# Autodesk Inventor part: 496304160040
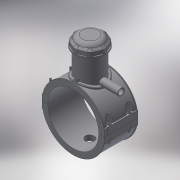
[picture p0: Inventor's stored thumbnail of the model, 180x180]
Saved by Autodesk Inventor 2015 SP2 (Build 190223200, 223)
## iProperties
Created: 2017-07
Part Number: 496304160040
Material: Generic
Description: PLASSON TAPPING SADDLE 160x40
Document SubType Name: Modeling
Designer: KIM
Mass: 1043.31 g
Surface Area: 2388.5 cm^2
Volume: 1043.31 cm^3
Density: 1 g/cm^3
Appearance: Default
Author: KIM
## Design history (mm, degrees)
derived "496304.ipt"
feature "Solid1::496304.ipt"
feature "Solid2::496304.ipt"
feature "Solid4::496304.ipt"
feature "Solid5::496304.ipt"
tag "TaggingFeature1"
body "Solid1"
body "Solid2"
other parameters: "B_" = 199, "L_" = 118, "d_t" = 6, "H_2" = 138, "H_1" = 21, "H_" = 157, "d1" = 182.4, "d148" = 2.4, "d160" = 2.4, "d169" = 3.375, "d192" = 6.3, "d2" = 199, "d4" = 118, "d5" = 0, "d6" = 0.1, "d8" = 0, "d19" = 6, "d20" = 6, "d21" = 70.8, "d23" = 0, "d24" = 35.4, "d26" = 0, "d29" = 3, "d30" = 53.33333, "d31" = 6, "d32" = 0, "d33" = 0, "d34" = 0.6, "d40" = 94.848, "d41" = 72, "d43" = 0, "d45" = 0, "d47" = 162, "d70" = 15, "d72" = 0, "d73" = 6, "d75" = 5, "d76" = 0, "d77" = 8, "d79" = 15, "d80" = 47.2, "d82" = 5 deg, "d84" = 4, "d85" = 14, "d86" = 0, "d87" = 3, "d88" = 0, "d89" = 1, "d90" = 1, "d91" = 94.4, "d92" = 0, "d93" = 0.5, "d94" = 84.21053, "d96" = 186.048, "d97" = 2.36, "d98" = 0, "d102" = 1.6, "d120" = 140 deg, "d121" = 24.228, "d122" = 20 deg, "d123" = 364.8, "d124" = 109.44, "d126" = 0, "d143" = 164.8, "d145" = 17.23077, "d149" = 2.4, "d150" = 18.95385, "d153" = 118, "d154" = 0, "d156" = 91.2, "d157" = 160 deg, "d159" = 4.48, "d161" = 2.4, "d162" = 70.8, "d163" = 0, "d167" = 16, "d168" = 88.97561, "d170" = 3.375, "d172" = 0, "d173" = 1, "d176" = 20 deg, "d177" = 11.2, "d178" = 22.4, "d180" = 0, "d183" = 8.96, "d184" = 8.96, "d185" = 38.35, "d186" = 38.35, "d187" = 91.2, "d188" = 6.72, "d189" = 11.2, "d190" = 0, "d191" = 136.8, "d193" = 6.3, "d194" = 4.13, "d195" = 90 deg, "d197" = 0, "d199" = 0, "d200" = 11.2, "d202" = 0, "d203" = 138, "d204" = 68.4, "d205" = 50.4, "d206" = 61.2, "d207" = 103.5, "d208" = 107.64, "d209" = 128.34, "d210" = 61.92, "d211" = 72, "d212" = 57.6, "d213" = 0.9, "d216" = 0, "d217" = 16, "d218" = 16, "d219" = 3.2, "d224" = 0, "d230" = 3.2, "d233" = 6, "d236" = 99.5, "d237" = 35.4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
